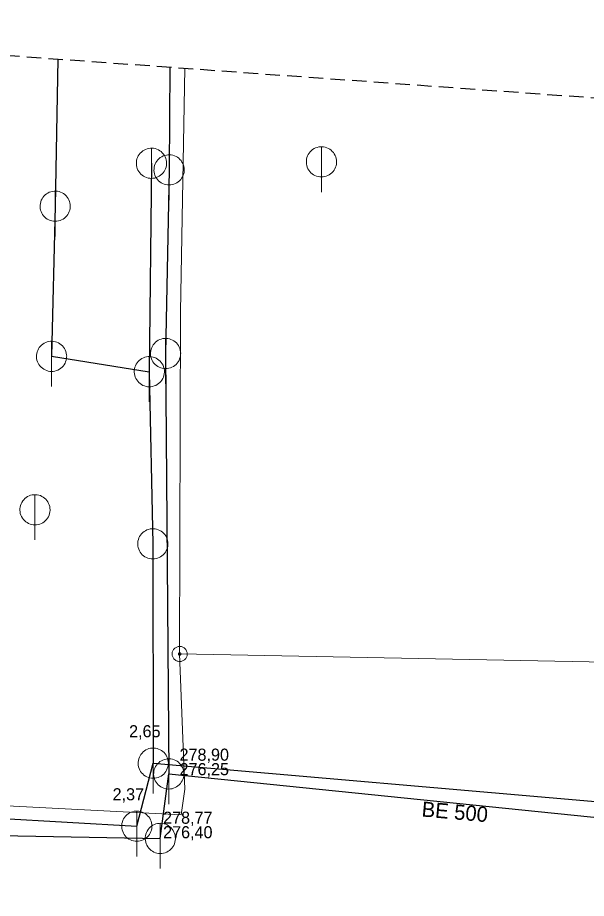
# Model space of a CAD drawing. Extents: x -725153 to -724843, y -978146 to -977794.
# Drawn here: x -725090.7 to -725053.1, y -977852.8 to -977794.5 of the extents above; entities that cross this region are included whole.
import ezdxf

# ---------------------------------------------------------------- set-up
doc = ezdxf.new("R2010")
doc.units = 0
doc.header["$LTSCALE"] = 0.32
doc.linetypes.add('MEDIUM_DASHED', pattern=[4.5, 3, -1.5])
doc.layers.add('1', color=7, linetype='Continuous')
for name, color, linetype, lineweight in [('13', 7, 'Continuous', 13), ('14', 7, 'Continuous', 25), ('22', 7, 'Continuous', 13), ('47', 7, 'Continuous', 13), ('63', 7, 'MEDIUM_DASHED', 25)]:
    doc.layers.add(name, color=color, linetype=linetype, lineweight=lineweight)

msp = doc.modelspace()

# ---------------------------------------------------------------- linework, layer by layer
at = {"layer": '13'}
msp.add_line((-725010.03, -977837.91), (-725080.007, -977836.588), dxfattribs=at)
for points in [[(-725079.667, -977797.8), (-725079.952, -977813.94), (-725080.007, -977836.588)], [(-725080.007, -977836.588), (-725079.662, -977845.545), (-725079.899, -977847.244), (-725098.287, -977846.293), (-725111.066, -977845.307), (-725122.792, -977843.37), (-725126.038, -977842.611)]]:
    msp.add_lwpolyline(points, dxfattribs=at)
at = {"layer": '14'}
for p, q in [((-725088.075, -977797.193), (-725088.25, -977806.94)), ((-725080.664, -977797.728), (-725080.708, -977804.533)), ((-725081.877, -977804.095), (-725082.017, -977817.895)), ((-725080.708, -977804.533), (-725080.94, -977816.69)), ((-725088.25, -977806.94), (-725088.489, -977816.879)), ((-725088.489, -977816.879), (-725082.017, -977817.895)), ((-725080.94, -977816.69), (-725080.73, -977844.53)), ((-725082.017, -977817.895), (-725081.787, -977829.295)), ((-725081.787, -977829.295), (-725081.757, -977843.815)), ((-725082.847, -977847.989), (-725081.757, -977843.815)), ((-725081.757, -977843.815), (-725042.36, -977847.23)), ((-725081.29, -977848.8), (-725080.73, -977844.53)), ((-725080.73, -977844.53), (-725042.11, -977848.46)), ((-725098, -977847.11), (-725082.847, -977847.989)), ((-725091.887, -977848.605), (-725081.29, -977848.8))]:
    msp.add_line(p, q, dxfattribs=at)
at = {"layer": '22'}
for p, q in [((-725081.877, -977806.095), (-725081.876, -977803.095)), ((-725070.62, -977806), (-725070.619, -977803)), ((-725080.708, -977806.533), (-725080.707, -977803.533)), ((-725088.25, -977808.94), (-725088.249, -977805.94)), ((-725088.489, -977818.879), (-725088.488, -977815.879)), ((-725080.94, -977818.69), (-725080.939, -977815.69)), ((-725082.017, -977819.895), (-725082.016, -977816.895)), ((-725089.59, -977829.039), (-725089.589, -977826.039)), ((-725081.787, -977831.295), (-725081.786, -977828.295)), ((-725081.757, -977845.815), (-725081.756, -977842.815)), ((-725080.73, -977846.53), (-725080.729, -977843.53)), ((-725082.847, -977849.989), (-725082.846, -977846.989)), ((-725081.29, -977850.8), (-725081.289, -977847.8))]:
    msp.add_line(p, q, dxfattribs=at)
for points in [[(-725080.877, -977804.095), (-725080.882, -977803.986), (-725080.9, -977803.878), (-725080.93, -977803.772), (-725080.97, -977803.671), (-725081.022, -977803.574), (-725081.084, -977803.484), (-725081.156, -977803.401), (-725081.236, -977803.327), (-725081.324, -977803.261), (-725081.418, -977803.206), (-725081.518, -977803.161), (-725081.623, -977803.128), (-725081.73, -977803.106), (-725081.839, -977803.096), (-725081.949, -977803.098), (-725082.057, -977803.112), (-725082.164, -977803.137), (-725082.267, -977803.174), (-725082.365, -977803.223), (-725082.457, -977803.281), (-725082.543, -977803.35), (-725082.62, -977803.427), (-725082.689, -977803.513), (-725082.748, -977803.605), (-725082.796, -977803.703), (-725082.833, -977803.806), (-725082.859, -977803.913), (-725082.873, -977804.021), (-725082.876, -977804.131), (-725082.866, -977804.24), (-725082.845, -977804.347), (-725082.811, -977804.451), (-725082.767, -977804.551), (-725082.712, -977804.646), (-725082.646, -977804.734), (-725082.572, -977804.814), (-725082.489, -977804.886), (-725082.399, -977804.948), (-725082.303, -977805), (-725082.201, -977805.041), (-725082.096, -977805.071), (-725081.988, -977805.089), (-725081.878, -977805.095), (-725081.769, -977805.089), (-725081.661, -977805.071), (-725081.556, -977805.042), (-725081.454, -977805.001), (-725081.357, -977804.949), (-725081.267, -977804.887), (-725081.184, -977804.816), (-725081.109, -977804.736), (-725081.044, -977804.648), (-725080.988, -977804.554), (-725080.944, -977804.454), (-725080.91, -977804.35), (-725080.888, -977804.242), (-725080.878, -977804.133)], [(-725069.62, -977804), (-725069.625, -977803.891), (-725069.643, -977803.783), (-725069.673, -977803.677), (-725069.713, -977803.576), (-725069.765, -977803.479), (-725069.827, -977803.389), (-725069.899, -977803.306), (-725069.979, -977803.232), (-725070.067, -977803.166), (-725070.161, -977803.111), (-725070.261, -977803.066), (-725070.366, -977803.033), (-725070.473, -977803.011), (-725070.582, -977803.001), (-725070.692, -977803.003), (-725070.8, -977803.017), (-725070.907, -977803.042), (-725071.01, -977803.079), (-725071.108, -977803.128), (-725071.2, -977803.186), (-725071.286, -977803.255), (-725071.363, -977803.332), (-725071.432, -977803.418), (-725071.491, -977803.51), (-725071.539, -977803.608), (-725071.576, -977803.711), (-725071.602, -977803.818), (-725071.616, -977803.926), (-725071.619, -977804.036), (-725071.609, -977804.145), (-725071.588, -977804.252), (-725071.554, -977804.356), (-725071.51, -977804.456), (-725071.455, -977804.551), (-725071.389, -977804.639), (-725071.315, -977804.719), (-725071.232, -977804.791), (-725071.142, -977804.853), (-725071.046, -977804.905), (-725070.944, -977804.946), (-725070.839, -977804.976), (-725070.731, -977804.994), (-725070.621, -977805), (-725070.512, -977804.994), (-725070.404, -977804.976), (-725070.299, -977804.947), (-725070.197, -977804.906), (-725070.1, -977804.854), (-725070.01, -977804.792), (-725069.927, -977804.721), (-725069.852, -977804.641), (-725069.787, -977804.553), (-725069.731, -977804.459), (-725069.687, -977804.359), (-725069.653, -977804.255), (-725069.631, -977804.147), (-725069.621, -977804.038)], [(-725079.708, -977804.533), (-725079.713, -977804.424), (-725079.731, -977804.316), (-725079.761, -977804.21), (-725079.801, -977804.109), (-725079.853, -977804.012), (-725079.915, -977803.922), (-725079.987, -977803.839), (-725080.067, -977803.765), (-725080.155, -977803.699), (-725080.249, -977803.644), (-725080.349, -977803.599), (-725080.454, -977803.566), (-725080.561, -977803.544), (-725080.67, -977803.534), (-725080.78, -977803.536), (-725080.888, -977803.55), (-725080.995, -977803.575), (-725081.098, -977803.612), (-725081.196, -977803.661), (-725081.288, -977803.719), (-725081.374, -977803.788), (-725081.451, -977803.865), (-725081.52, -977803.951), (-725081.579, -977804.043), (-725081.627, -977804.141), (-725081.664, -977804.244), (-725081.69, -977804.351), (-725081.704, -977804.459), (-725081.707, -977804.569), (-725081.697, -977804.678), (-725081.676, -977804.785), (-725081.642, -977804.889), (-725081.598, -977804.989), (-725081.543, -977805.084), (-725081.477, -977805.172), (-725081.403, -977805.252), (-725081.32, -977805.324), (-725081.23, -977805.386), (-725081.134, -977805.438), (-725081.032, -977805.479), (-725080.927, -977805.509), (-725080.819, -977805.527), (-725080.709, -977805.533), (-725080.6, -977805.527), (-725080.492, -977805.509), (-725080.387, -977805.48), (-725080.285, -977805.439), (-725080.188, -977805.387), (-725080.098, -977805.325), (-725080.015, -977805.254), (-725079.94, -977805.174), (-725079.875, -977805.086), (-725079.819, -977804.992), (-725079.775, -977804.892), (-725079.741, -977804.788), (-725079.719, -977804.68), (-725079.709, -977804.571)], [(-725087.25, -977806.94), (-725087.255, -977806.831), (-725087.273, -977806.723), (-725087.303, -977806.617), (-725087.343, -977806.516), (-725087.395, -977806.419), (-725087.457, -977806.329), (-725087.529, -977806.246), (-725087.609, -977806.172), (-725087.697, -977806.106), (-725087.791, -977806.051), (-725087.891, -977806.006), (-725087.996, -977805.973), (-725088.103, -977805.951), (-725088.212, -977805.941), (-725088.322, -977805.943), (-725088.43, -977805.957), (-725088.537, -977805.982), (-725088.64, -977806.019), (-725088.738, -977806.068), (-725088.83, -977806.126), (-725088.916, -977806.195), (-725088.993, -977806.272), (-725089.062, -977806.358), (-725089.121, -977806.45), (-725089.169, -977806.548), (-725089.206, -977806.651), (-725089.232, -977806.758), (-725089.246, -977806.866), (-725089.249, -977806.976), (-725089.239, -977807.085), (-725089.218, -977807.192), (-725089.184, -977807.296), (-725089.14, -977807.396), (-725089.085, -977807.491), (-725089.019, -977807.579), (-725088.945, -977807.659), (-725088.862, -977807.731), (-725088.772, -977807.793), (-725088.676, -977807.845), (-725088.574, -977807.886), (-725088.469, -977807.916), (-725088.361, -977807.934), (-725088.251, -977807.94), (-725088.142, -977807.934), (-725088.034, -977807.916), (-725087.929, -977807.887), (-725087.827, -977807.846), (-725087.73, -977807.794), (-725087.64, -977807.732), (-725087.557, -977807.661), (-725087.482, -977807.581), (-725087.417, -977807.493), (-725087.361, -977807.399), (-725087.317, -977807.299), (-725087.283, -977807.195), (-725087.261, -977807.087), (-725087.251, -977806.978)], [(-725087.489, -977816.879), (-725087.494, -977816.77), (-725087.512, -977816.662), (-725087.542, -977816.556), (-725087.582, -977816.455), (-725087.634, -977816.358), (-725087.696, -977816.268), (-725087.768, -977816.185), (-725087.848, -977816.111), (-725087.936, -977816.045), (-725088.03, -977815.99), (-725088.13, -977815.945), (-725088.235, -977815.912), (-725088.342, -977815.89), (-725088.451, -977815.88), (-725088.561, -977815.882), (-725088.669, -977815.896), (-725088.776, -977815.921), (-725088.879, -977815.958), (-725088.977, -977816.007), (-725089.069, -977816.065), (-725089.155, -977816.134), (-725089.232, -977816.211), (-725089.301, -977816.297), (-725089.36, -977816.389), (-725089.408, -977816.487), (-725089.445, -977816.59), (-725089.471, -977816.697), (-725089.485, -977816.805), (-725089.488, -977816.915), (-725089.478, -977817.024), (-725089.457, -977817.131), (-725089.423, -977817.235), (-725089.379, -977817.335), (-725089.324, -977817.43), (-725089.258, -977817.518), (-725089.184, -977817.598), (-725089.101, -977817.67), (-725089.011, -977817.732), (-725088.915, -977817.784), (-725088.813, -977817.825), (-725088.708, -977817.855), (-725088.6, -977817.873), (-725088.49, -977817.879), (-725088.381, -977817.873), (-725088.273, -977817.855), (-725088.168, -977817.826), (-725088.066, -977817.785), (-725087.969, -977817.733), (-725087.879, -977817.671), (-725087.796, -977817.6), (-725087.721, -977817.52), (-725087.656, -977817.432), (-725087.6, -977817.338), (-725087.556, -977817.238), (-725087.522, -977817.134), (-725087.5, -977817.026), (-725087.49, -977816.917)], [(-725079.94, -977816.69), (-725079.945, -977816.581), (-725079.963, -977816.473), (-725079.993, -977816.367), (-725080.033, -977816.266), (-725080.085, -977816.169), (-725080.147, -977816.079), (-725080.219, -977815.996), (-725080.299, -977815.922), (-725080.387, -977815.856), (-725080.481, -977815.801), (-725080.581, -977815.756), (-725080.686, -977815.723), (-725080.793, -977815.701), (-725080.902, -977815.691), (-725081.012, -977815.693), (-725081.12, -977815.707), (-725081.227, -977815.732), (-725081.33, -977815.769), (-725081.428, -977815.818), (-725081.52, -977815.876), (-725081.606, -977815.945), (-725081.683, -977816.022), (-725081.752, -977816.108), (-725081.811, -977816.2), (-725081.859, -977816.298), (-725081.896, -977816.401), (-725081.922, -977816.508), (-725081.936, -977816.616), (-725081.939, -977816.726), (-725081.929, -977816.835), (-725081.908, -977816.942), (-725081.874, -977817.046), (-725081.83, -977817.146), (-725081.775, -977817.241), (-725081.709, -977817.329), (-725081.635, -977817.409), (-725081.552, -977817.481), (-725081.462, -977817.543), (-725081.366, -977817.595), (-725081.264, -977817.636), (-725081.159, -977817.666), (-725081.051, -977817.684), (-725080.941, -977817.69), (-725080.832, -977817.684), (-725080.724, -977817.666), (-725080.619, -977817.637), (-725080.517, -977817.596), (-725080.42, -977817.544), (-725080.33, -977817.482), (-725080.247, -977817.411), (-725080.172, -977817.331), (-725080.107, -977817.243), (-725080.051, -977817.149), (-725080.007, -977817.049), (-725079.973, -977816.945), (-725079.951, -977816.837), (-725079.941, -977816.728)], [(-725081.017, -977817.895), (-725081.022, -977817.786), (-725081.04, -977817.678), (-725081.07, -977817.572), (-725081.11, -977817.471), (-725081.162, -977817.374), (-725081.224, -977817.284), (-725081.296, -977817.201), (-725081.376, -977817.127), (-725081.464, -977817.061), (-725081.558, -977817.006), (-725081.658, -977816.961), (-725081.763, -977816.928), (-725081.87, -977816.906), (-725081.979, -977816.896), (-725082.089, -977816.898), (-725082.197, -977816.912), (-725082.304, -977816.937), (-725082.407, -977816.974), (-725082.505, -977817.023), (-725082.597, -977817.081), (-725082.683, -977817.15), (-725082.76, -977817.227), (-725082.829, -977817.313), (-725082.888, -977817.405), (-725082.936, -977817.503), (-725082.973, -977817.606), (-725082.999, -977817.713), (-725083.013, -977817.821), (-725083.016, -977817.931), (-725083.006, -977818.04), (-725082.985, -977818.147), (-725082.951, -977818.251), (-725082.907, -977818.351), (-725082.852, -977818.446), (-725082.786, -977818.534), (-725082.712, -977818.614), (-725082.629, -977818.686), (-725082.539, -977818.748), (-725082.443, -977818.8), (-725082.341, -977818.841), (-725082.236, -977818.871), (-725082.128, -977818.889), (-725082.018, -977818.895), (-725081.909, -977818.889), (-725081.801, -977818.871), (-725081.696, -977818.842), (-725081.594, -977818.801), (-725081.497, -977818.749), (-725081.407, -977818.687), (-725081.324, -977818.616), (-725081.249, -977818.536), (-725081.184, -977818.448), (-725081.128, -977818.354), (-725081.084, -977818.254), (-725081.05, -977818.15), (-725081.028, -977818.042), (-725081.018, -977817.933)], [(-725088.59, -977827.039), (-725088.595, -977826.93), (-725088.613, -977826.822), (-725088.643, -977826.716), (-725088.683, -977826.615), (-725088.735, -977826.518), (-725088.797, -977826.428), (-725088.869, -977826.345), (-725088.949, -977826.271), (-725089.037, -977826.205), (-725089.131, -977826.15), (-725089.231, -977826.105), (-725089.336, -977826.072), (-725089.443, -977826.05), (-725089.552, -977826.04), (-725089.662, -977826.042), (-725089.77, -977826.056), (-725089.877, -977826.081), (-725089.98, -977826.118), (-725090.078, -977826.167), (-725090.17, -977826.225), (-725090.256, -977826.294), (-725090.333, -977826.371), (-725090.402, -977826.457), (-725090.461, -977826.549), (-725090.509, -977826.647), (-725090.546, -977826.75), (-725090.572, -977826.857), (-725090.586, -977826.965), (-725090.589, -977827.075), (-725090.579, -977827.184), (-725090.558, -977827.291), (-725090.524, -977827.395), (-725090.48, -977827.495), (-725090.425, -977827.59), (-725090.359, -977827.678), (-725090.285, -977827.758), (-725090.202, -977827.83), (-725090.112, -977827.892), (-725090.016, -977827.944), (-725089.914, -977827.985), (-725089.809, -977828.015), (-725089.701, -977828.033), (-725089.591, -977828.039), (-725089.482, -977828.033), (-725089.374, -977828.015), (-725089.269, -977827.986), (-725089.167, -977827.945), (-725089.07, -977827.893), (-725088.98, -977827.831), (-725088.897, -977827.76), (-725088.822, -977827.68), (-725088.757, -977827.592), (-725088.701, -977827.498), (-725088.657, -977827.398), (-725088.623, -977827.294), (-725088.601, -977827.186), (-725088.591, -977827.077)], [(-725080.787, -977829.295), (-725080.792, -977829.186), (-725080.81, -977829.078), (-725080.84, -977828.972), (-725080.88, -977828.871), (-725080.932, -977828.774), (-725080.994, -977828.684), (-725081.066, -977828.601), (-725081.146, -977828.527), (-725081.234, -977828.461), (-725081.328, -977828.406), (-725081.428, -977828.361), (-725081.533, -977828.328), (-725081.64, -977828.306), (-725081.749, -977828.296), (-725081.859, -977828.298), (-725081.967, -977828.312), (-725082.074, -977828.337), (-725082.177, -977828.374), (-725082.275, -977828.423), (-725082.367, -977828.481), (-725082.453, -977828.55), (-725082.53, -977828.627), (-725082.599, -977828.713), (-725082.658, -977828.805), (-725082.706, -977828.903), (-725082.743, -977829.006), (-725082.769, -977829.113), (-725082.783, -977829.221), (-725082.786, -977829.331), (-725082.776, -977829.44), (-725082.755, -977829.547), (-725082.721, -977829.651), (-725082.677, -977829.751), (-725082.622, -977829.846), (-725082.556, -977829.934), (-725082.482, -977830.014), (-725082.399, -977830.086), (-725082.309, -977830.148), (-725082.213, -977830.2), (-725082.111, -977830.241), (-725082.006, -977830.271), (-725081.898, -977830.289), (-725081.788, -977830.295), (-725081.679, -977830.289), (-725081.571, -977830.271), (-725081.466, -977830.242), (-725081.364, -977830.201), (-725081.267, -977830.149), (-725081.177, -977830.087), (-725081.094, -977830.016), (-725081.019, -977829.936), (-725080.954, -977829.848), (-725080.898, -977829.754), (-725080.854, -977829.654), (-725080.82, -977829.55), (-725080.798, -977829.442), (-725080.788, -977829.333)], [(-725080.757, -977843.815), (-725080.762, -977843.706), (-725080.78, -977843.598), (-725080.81, -977843.492), (-725080.85, -977843.391), (-725080.902, -977843.294), (-725080.964, -977843.204), (-725081.036, -977843.121), (-725081.116, -977843.047), (-725081.204, -977842.981), (-725081.298, -977842.926), (-725081.398, -977842.881), (-725081.503, -977842.848), (-725081.61, -977842.826), (-725081.719, -977842.816), (-725081.829, -977842.818), (-725081.937, -977842.832), (-725082.044, -977842.857), (-725082.147, -977842.894), (-725082.245, -977842.943), (-725082.337, -977843.001), (-725082.423, -977843.07), (-725082.5, -977843.147), (-725082.569, -977843.233), (-725082.628, -977843.325), (-725082.676, -977843.423), (-725082.713, -977843.526), (-725082.739, -977843.633), (-725082.753, -977843.741), (-725082.756, -977843.851), (-725082.746, -977843.96), (-725082.725, -977844.067), (-725082.691, -977844.171), (-725082.647, -977844.271), (-725082.592, -977844.366), (-725082.526, -977844.454), (-725082.452, -977844.534), (-725082.369, -977844.606), (-725082.279, -977844.668), (-725082.183, -977844.72), (-725082.081, -977844.761), (-725081.976, -977844.791), (-725081.868, -977844.809), (-725081.758, -977844.815), (-725081.649, -977844.809), (-725081.541, -977844.791), (-725081.436, -977844.762), (-725081.334, -977844.721), (-725081.237, -977844.669), (-725081.147, -977844.607), (-725081.064, -977844.536), (-725080.989, -977844.456), (-725080.924, -977844.368), (-725080.868, -977844.274), (-725080.824, -977844.174), (-725080.79, -977844.07), (-725080.768, -977843.962), (-725080.758, -977843.853)], [(-725079.73, -977844.53), (-725079.735, -977844.421), (-725079.753, -977844.313), (-725079.783, -977844.207), (-725079.823, -977844.106), (-725079.875, -977844.009), (-725079.937, -977843.919), (-725080.009, -977843.836), (-725080.089, -977843.762), (-725080.177, -977843.696), (-725080.271, -977843.641), (-725080.371, -977843.596), (-725080.476, -977843.563), (-725080.583, -977843.541), (-725080.692, -977843.531), (-725080.802, -977843.533), (-725080.91, -977843.547), (-725081.017, -977843.572), (-725081.12, -977843.609), (-725081.218, -977843.658), (-725081.31, -977843.716), (-725081.396, -977843.785), (-725081.473, -977843.862), (-725081.542, -977843.948), (-725081.601, -977844.04), (-725081.649, -977844.138), (-725081.686, -977844.241), (-725081.712, -977844.348), (-725081.726, -977844.456), (-725081.729, -977844.566), (-725081.719, -977844.675), (-725081.698, -977844.782), (-725081.664, -977844.886), (-725081.62, -977844.986), (-725081.565, -977845.081), (-725081.499, -977845.169), (-725081.425, -977845.249), (-725081.342, -977845.321), (-725081.252, -977845.383), (-725081.156, -977845.435), (-725081.054, -977845.476), (-725080.949, -977845.506), (-725080.841, -977845.524), (-725080.731, -977845.53), (-725080.622, -977845.524), (-725080.514, -977845.506), (-725080.409, -977845.477), (-725080.307, -977845.436), (-725080.21, -977845.384), (-725080.12, -977845.322), (-725080.037, -977845.251), (-725079.962, -977845.171), (-725079.897, -977845.083), (-725079.841, -977844.989), (-725079.797, -977844.889), (-725079.763, -977844.785), (-725079.741, -977844.677), (-725079.731, -977844.568)], [(-725081.847, -977847.989), (-725081.852, -977847.88), (-725081.87, -977847.772), (-725081.9, -977847.666), (-725081.94, -977847.565), (-725081.992, -977847.468), (-725082.054, -977847.378), (-725082.126, -977847.295), (-725082.206, -977847.221), (-725082.294, -977847.155), (-725082.388, -977847.1), (-725082.488, -977847.055), (-725082.593, -977847.022), (-725082.7, -977847), (-725082.809, -977846.99), (-725082.919, -977846.992), (-725083.027, -977847.006), (-725083.134, -977847.031), (-725083.237, -977847.068), (-725083.335, -977847.117), (-725083.427, -977847.175), (-725083.513, -977847.244), (-725083.59, -977847.321), (-725083.659, -977847.407), (-725083.718, -977847.499), (-725083.766, -977847.597), (-725083.803, -977847.7), (-725083.829, -977847.807), (-725083.843, -977847.915), (-725083.846, -977848.025), (-725083.836, -977848.134), (-725083.815, -977848.241), (-725083.781, -977848.345), (-725083.737, -977848.445), (-725083.682, -977848.54), (-725083.616, -977848.628), (-725083.542, -977848.708), (-725083.459, -977848.78), (-725083.369, -977848.842), (-725083.273, -977848.894), (-725083.171, -977848.935), (-725083.066, -977848.965), (-725082.958, -977848.983), (-725082.848, -977848.989), (-725082.739, -977848.983), (-725082.631, -977848.965), (-725082.526, -977848.936), (-725082.424, -977848.895), (-725082.327, -977848.843), (-725082.237, -977848.781), (-725082.154, -977848.71), (-725082.079, -977848.63), (-725082.014, -977848.542), (-725081.958, -977848.448), (-725081.914, -977848.348), (-725081.88, -977848.244), (-725081.858, -977848.136), (-725081.848, -977848.027)], [(-725080.29, -977848.8), (-725080.295, -977848.691), (-725080.313, -977848.583), (-725080.343, -977848.477), (-725080.383, -977848.376), (-725080.435, -977848.279), (-725080.497, -977848.189), (-725080.569, -977848.106), (-725080.649, -977848.032), (-725080.737, -977847.966), (-725080.831, -977847.911), (-725080.931, -977847.866), (-725081.036, -977847.833), (-725081.143, -977847.811), (-725081.252, -977847.801), (-725081.362, -977847.803), (-725081.47, -977847.817), (-725081.577, -977847.842), (-725081.68, -977847.879), (-725081.778, -977847.928), (-725081.87, -977847.986), (-725081.956, -977848.055), (-725082.033, -977848.132), (-725082.102, -977848.218), (-725082.161, -977848.31), (-725082.209, -977848.408), (-725082.246, -977848.511), (-725082.272, -977848.618), (-725082.286, -977848.726), (-725082.289, -977848.836), (-725082.279, -977848.945), (-725082.258, -977849.052), (-725082.224, -977849.156), (-725082.18, -977849.256), (-725082.125, -977849.351), (-725082.059, -977849.439), (-725081.985, -977849.519), (-725081.902, -977849.591), (-725081.812, -977849.653), (-725081.716, -977849.705), (-725081.614, -977849.746), (-725081.509, -977849.776), (-725081.401, -977849.794), (-725081.291, -977849.8), (-725081.182, -977849.794), (-725081.074, -977849.776), (-725080.969, -977849.747), (-725080.867, -977849.706), (-725080.77, -977849.654), (-725080.68, -977849.592), (-725080.597, -977849.521), (-725080.522, -977849.441), (-725080.457, -977849.353), (-725080.401, -977849.259), (-725080.357, -977849.159), (-725080.323, -977849.055), (-725080.301, -977848.947), (-725080.291, -977848.838)]]:
    msp.add_lwpolyline(points, close=True, dxfattribs=at)
at = {"layer": '47'}
for points in [[(-725080.506, -977836.578), (-725080.504, -977836.63), (-725080.497, -977836.682), (-725080.484, -977836.733), (-725080.467, -977836.782), (-725080.444, -977836.829), (-725080.416, -977836.874), (-725080.384, -977836.914), (-725080.347, -977836.952), (-725080.308, -977836.986), (-725080.265, -977837.016), (-725080.218, -977837.041), (-725080.169, -977837.06), (-725080.12, -977837.074), (-725080.068, -977837.083), (-725080.016, -977837.087), (-725079.964, -977837.085), (-725079.912, -977837.078), (-725079.86, -977837.065), (-725079.812, -977837.048), (-725079.765, -977837.025), (-725079.72, -977836.997), (-725079.679, -977836.965), (-725079.641, -977836.928), (-725079.607, -977836.889), (-725079.578, -977836.846), (-725079.553, -977836.799), (-725079.533, -977836.75), (-725079.52, -977836.701), (-725079.511, -977836.649), (-725079.507, -977836.597), (-725079.509, -977836.545), (-725079.516, -977836.493), (-725079.528, -977836.442), (-725079.546, -977836.393), (-725079.569, -977836.346), (-725079.596, -977836.301), (-725079.628, -977836.26), (-725079.665, -977836.222), (-725079.705, -977836.188), (-725079.748, -977836.159), (-725079.795, -977836.134), (-725079.843, -977836.115), (-725079.893, -977836.101), (-725079.945, -977836.092), (-725079.997, -977836.088), (-725080.049, -977836.09), (-725080.101, -977836.097), (-725080.151, -977836.109), (-725080.201, -977836.127), (-725080.248, -977836.15), (-725080.293, -977836.177), (-725080.333, -977836.209), (-725080.371, -977836.246), (-725080.405, -977836.286), (-725080.435, -977836.329), (-725080.46, -977836.376), (-725080.478, -977836.424), (-725080.493, -977836.474), (-725080.502, -977836.526)], [(-725080.088, -977836.586), (-725080.089, -977836.595), (-725080.087, -977836.603), (-725080.085, -977836.611), (-725080.082, -977836.619), (-725080.078, -977836.627), (-725080.073, -977836.634), (-725080.069, -977836.641), (-725080.063, -977836.647), (-725080.056, -977836.653), (-725080.049, -977836.658), (-725080.041, -977836.662), (-725080.033, -977836.665), (-725080.025, -977836.667), (-725080.017, -977836.669), (-725080.008, -977836.669), (-725079.999, -977836.67), (-725079.991, -977836.668), (-725079.983, -977836.666), (-725079.975, -977836.663), (-725079.967, -977836.659), (-725079.96, -977836.654), (-725079.953, -977836.65), (-725079.947, -977836.644), (-725079.94, -977836.637), (-725079.936, -977836.63), (-725079.932, -977836.622), (-725079.929, -977836.614), (-725079.927, -977836.606), (-725079.925, -977836.598), (-725079.925, -977836.589), (-725079.924, -977836.58), (-725079.926, -977836.572), (-725079.928, -977836.564), (-725079.931, -977836.556), (-725079.935, -977836.548), (-725079.939, -977836.541), (-725079.944, -977836.534), (-725079.95, -977836.528), (-725079.957, -977836.521), (-725079.964, -977836.517), (-725079.972, -977836.513), (-725079.98, -977836.51), (-725079.988, -977836.508), (-725079.996, -977836.506), (-725080.005, -977836.506), (-725080.014, -977836.505), (-725080.022, -977836.507), (-725080.03, -977836.509), (-725080.038, -977836.512), (-725080.046, -977836.516), (-725080.053, -977836.52), (-725080.06, -977836.525), (-725080.066, -977836.531), (-725080.072, -977836.538), (-725080.077, -977836.545), (-725080.081, -977836.553), (-725080.084, -977836.561), (-725080.086, -977836.569), (-725080.088, -977836.577)]]:
    msp.add_lwpolyline(points, close=True, dxfattribs=at)
at = {"layer": '63'}
msp.add_lwpolyline([(-725126.038, -977904.704), (-725126.038, -977794.451), (-724874.829, -977812.594), (-724855.29, -977827.945), (-724842.73, -977919.358), (-724859.477, -977998.21), (-724911.114, -978092.413), (-724961.356, -978146.144), (-725152.554, -978126.605)], close=True, dxfattribs=at)

# ---------------------------------------------------------------- texts
at = {"layer": '1'}
for s, p in [('2,65', (-725083.356, -977842.103)), ('2,37', (-725084.446, -977846.277))]:
    msp.add_text(s, height=0.8, dxfattribs=at).set_placement(p)
msp.add_text('BE 500', height=1, rotation=355, dxfattribs=at).set_placement((-725064.011, -977847.345))
at = {"layer": '22'}
for s, p in [('278,90', (-725080.014, -977843.654)), ('276,25', (-725080.014, -977844.614)), ('278,77', (-725081.104, -977847.829)), ('276,40', (-725081.104, -977848.789))]:
    msp.add_text(s, height=0.8, dxfattribs=at).set_placement(p)

doc.saveas('drawing.dxf')
